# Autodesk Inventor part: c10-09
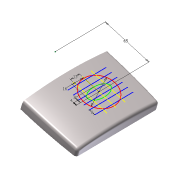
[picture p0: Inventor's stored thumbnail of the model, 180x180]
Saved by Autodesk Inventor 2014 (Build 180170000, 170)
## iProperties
Created: 2010-12
Part Number: c10-09
Material: Generic
Document SubType Name: Modeling
Designer: Thom Tremblay
Density: 1 g/cm^3
Appearance: Generic
Author: Thom Tremblay
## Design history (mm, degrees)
sketch "Sketch1"
  geometry: L1 (-60, -12)-(60, -12); L2 (60, -12)-(60, 12); L3 (60, 12)-(-60, 12); L4 (-60, 12)-(-60, -12); A1 r 350 centre (0, -332.819) between (60, 12) and (-60, 12); A2 r 350 centre (0, 332.819) between (-60, -12) and (60, -12); 3 further points
  constraints: 8 end point, 4 point on circle, 2 centre point, 2 midpoint, 2 parallel, 1 equal radius, 1 horizontal, 1 horizontal alignment, 1 perpendicular, 1 vertical alignment
  dimensions: "d0" = 120 distance of L3.end L2.end; "d1" = 24 distance of L2.end L1.end; "d2" = 350 radius of A1
workplane "Work Plane4"
sketch "Sketch5"
  geometry: L1 (-60, 12)-(-60, -12) reference; L2 (60, -12)-(60, 12) reference; L3 (-58, 10.314)-(-58, -10.314); L4 (58, -10.314)-(58, 10.314); A1 r 350 centre (0, 332.819) between (-60, -12) and (60, -12) reference; A2 r 350 centre (0, -332.819) between (60, 12) and (-60, 12) reference; A3 r 348 centre (0, 332.819) between (-58, -10.314) and (58, -10.314); A4 r 348 centre (0, -332.819) between (58, 10.314) and (-58, 10.314); 1 further point
  constraints: 4 end point, 4 point on circle, 2 centre point, 3 other
  dimensions: "d37" = 2 distance between parallel lines of L2 L4
sketch "Sketch6"
  geometry: L1 (-60, 0)-(60, 0); L2 (60, 0)-(58.843, 22.085); L3 (-60, 0)-(-58.779, 23.307); A1 r 691.758 centre (630.81, -36.204) between (-60, 0) and (-58, -100); A2 r 691.758 centre (-630.81, -36.204) between (58, -100) and (60, 0); 1 further point
  constraints: 6 end point, 4 point on circle, 2 centre point, 2 tangent, 1 horizontal
  dimensions: "d53" = 87 deg angle of L1 L3; "d54" = 87 deg angle of L1 L2 (= d53)
sketch "Sketch7"
  geometry: L1 (17.181, 0)-(12, 0) reference; L2 (15.181, -100)-(10.314, -100) reference; L3 (17.181, 0)-(16.768, 11.838); A1 r 911.322 centre (-893.585, -31.805) between (15.181, -100) and (17.181, 0); 1 further point
  constraints: 2 end point, 2 point on circle, 1 centre point, 1 tangent
  dimensions: "d56" = 88 deg angle of L1 L3
feature "LoftSrf2" sketch "Sketch5", "Sketch6", "Sketch7" dims "d57" = 0, "d58" = 90 deg, "d59" = 0, "d60" = 90 deg, "d61" = 0, "d62" = 90 deg, "d63" = 0, "d64" = 90 deg, "d65" = 0, "d66" = 90 deg
sketch "Sketch2"
  geometry: L1 (-75, -16)-(75, -16); L2 (-75, -60)-(75, -60); A1 r 183.781 centre (0, -183.781) between (75, -16) and (-75, -16); 2 further points
  constraints: 4 end point, 3 point on circle, 1 centre point, 1 coincident, 1 horizontal, 1 parallel
  dimensions: "d5" = 16 distance from line of point (0, 0) L1; "d7" = 60 distance from line of point (0, 0) L2; "d55" = 150 distance of L1.start L1.end
feature "RevolutionSrf1" sketch "Sketch2" dims angle "d8" = 40 deg
patch "Boundary Patch1" dims "d13" = 0, "d67" = 0, "d68" = 0, "d69" = 0, "d70" = 0
workplane "Work Plane1"
sketch "Sketch3"
  geometry: L1 (52, -85)-(52, -73); L2 (38, -73)-(38, -85); A1 r 7 centre (45, -73) between (52, -73) and (38, -73); A2 r 7 centre (45, -85) between (38, -85) and (52, -85); 1 further point
  constraints: 4 end point, 4 point on circle, 4 tangent, 2 centre point, 1 parallel, 1 vertical
  dimensions: "d15" = 12 distance of L1.start L1.end; "d16" = 7 radius of A1; "d50" = 45 horizontal distance of A1.centre point (0, 0); "d51" = 85 vertical distance of point (0, 0) A2.centre
extrude_surface "ExtrusionSrf2" sketch "Sketch3" dims "d19" = 14, "d20" = 5 deg
pattern_linear "Rectangular Pattern1" dims "d23" = 90
workplane "Work Plane2"
feature "Sculpt1"
sketch "Sketch4"
  geometry: L1 (-24.5, 6)-(24.5, 6); L2 (27.5, 3)-(27.5, -3); L3 (24.5, -6)-(-24.5, -6); L4 (-27.5, -3)-(-27.5, 3); A1 r 3 centre (-24.5, 3) between (-24.5, 6) and (-27.5, 3); A2 r 3 centre (24.5, 3) between (27.5, 3) and (24.5, 6); A3 r 3 centre (24.5, -3) between (24.5, -6) and (27.5, -3); A4 r 3 centre (-24.5, -3) between (-27.5, -3) and (-24.5, -6); 6 further points
  constraints: 8 end point, 8 point on circle, 8 tangent, 6 point on line, 4 centre point, 3 equal radius, 2 midpoint, 2 parallel, 1 horizontal, 1 horizontal alignment, 1 perpendicular, 1 vertical alignment
  dimensions: "d28" = 55 distance of point (27.5, -6) point (-27.5, -6); "d29" = 12 distance of point (27.5, 6) point (27.5, -6); "d30" = 3 radius of A1
extrude_surface "ExtrusionSrf6" sketch "Sketch4" dims "d31" = 14, "d32" = 45 deg
patch "Boundary Patch2" dims "d33" = 0, "d34" = 0
fillet "Fillet1" dims "d79" = 4, "d80" = 3, "d81" = 1
feature "Sculpt2"
node "Splitting Plane 1"
shell "Shell1" dims "d83" = 2
split "Split1"
  body "Solid1"
feature "Lip1" dims "d171" = 1, "d172" = 1, "d173" = 0, "d174" = 0, "d175" = 0, "d176" = 0
feature "Lip2" dims "d177" = 1, "d178" = 1, "d179" = 0, "d180" = 0, "d181" = 0, "d182" = 0.5
split "Split3"
  node "Back"
sketch "Sketch9"
  geometry: L1 (50.167, -73)-(50.167, -85) reference; L2 (39.833, -85)-(39.833, -73) reference; L3 (45, -73)-(45, -85); L4 (45, -85)-(39.833, -85); A1 r 5.167 centre (45, -73) between (50.167, -73) and (39.833, -73) reference; A2 r 5.167 centre (45, -85) between (39.833, -85) and (50.167, -85) reference; 5 further points
  constraints: 4 end point, 1 horizontal, 1 midpoint, 1 parallel, 1 perpendicular, 1 vertical, 3 other
  dimensions: "d86" = 90 distance of point (45, -79) point (-45, -79); "d89" = 40 distance of point (45, -79) point (45, -39)
  node "Projected Loop1"
feature "Boss1" dims "d92" = 0, "d93" = 0, "d94" = 7, "d95" = 2, "d96" = 0.5, "d97" = 6, "d98" = 1.25, "d99" = 3.5, "d100" = 2.5 deg, "d101" = 2.5 deg, "d102" = 2.5 deg, "d103" = 2.5 deg, "d104" = 90 deg, "d107" = 2, "d108" = 2, "d109" = 10, "d110" = 0, "d111" = 10 deg, "d112" = 2.5 deg, "d113" = 0, "d114" = 0, "d115" = 0, "d116" = 360 deg
feature "Boss2" dims "d117" = 3, "d118" = 0, "d119" = 6, "d120" = 3, "d121" = 9.5, "d122" = 2 deg, "d123" = 1 deg, "d126" = 2, "d127" = 2, "d128" = 10, "d129" = 0, "d130" = 10 deg, "d131" = 2.5 deg, "d132" = 0, "d133" = 0, "d134" = 0, "d135" = 360 deg
workplane "Work Plane6"
sketch "Sketch10"
  geometry: L1 (24, -85)-(-24, -85); L2 (-30, -79)-(-30, -51); L3 (-24, -45)-(24, -45); L4 (30, -51)-(30, -79); L5 (54.344, -100)-(-54.344, -100) reference; A1 r 6 centre (-24, -51) between (-24, -45) and (-30, -51); A2 r 6 centre (24, -51) between (30, -51) and (24, -45); A3 r 6 centre (24, -79) between (24, -85) and (30, -79); A4 r 6 centre (-24, -79) between (-30, -79) and (-24, -85); 5 further points
  constraints: 8 end point, 8 point on circle, 8 tangent, 6 point on line, 4 centre point, 3 equal radius, 2 parallel, 1 horizontal, 1 midpoint, 1 perpendicular, 1 vertical alignment
  dimensions: "d137" = 60 distance of point (-30, -45) point (30, -45); "d138" = 40 distance of point (-30, -85) point (-30, -45); "d139" = 15 distance between parallel lines of L5 L1; "d141" = 6 radius of A2
feature "Rest1" sketch "Sketch10" dims "d142" = 5, "d143" = 0, "d144" = 0, "d145" = 0, "d146" = 2 deg, "d147" = 2 deg, "d148" = 2
feature "Rule Fillet1" dims "d149" = 2, "d150" = 1
workplane "Work Plane7"
sketch "Sketch11" dims "d21" = 20, "d154" = 16, "d155" = 8, "d161" = 10, "d168" = 10
  geometry: L1 (-13, -39.858)-(-13, -90.142); L2 (-25.187, -85)-(29.449, -85); L3 (0, -39.858)-(0, -90.142); L4 (13, -39.858)-(13, -90.142); L5 (-25.187, -77)-(29.449, -77); L6 (-25.187, -69)-(29.449, -69); L7 (-25.187, -61)-(29.449, -61); L8 (-25.187, -53)-(29.449, -53); L9 (-25.187, -45)-(29.449, -45); C1 r 22.5 at (0, -65); 3 further points; 1 other entity
  constraints: 18 end point, 2 coincident, 2 vertical, 1 centre point, 1 horizontal, 1 midpoint, 1 perpendicular, 1 vertical alignment, 23 other
  dimensions: "d152" = 45 diameter of C1; "d153" = 65 distance of point (0, 0) C1.centre; "d158" = 13 distance of L1.start L3.start; "d165" = 8 distance of L2.start L5.start; "d170" = 4 distance from line of L7 point (0, -65)
body "Srf2"
body "Srf3"
body "Srf4"
body "Srf5"
body "Srf6"
body "Srf7"
body "Srf8"
body "Srf9"
body "Srf11"
feature "Stitch Surface1"
body "Srf12"
extrude_surface "ExtrusionSrf3"
extrude_surface "ExtrusionSrf4"
extrude_surface "ExtrusionSrf5"
node "Front"
node "Back - Top"
node "Back - Bottom"
other parameters: "d14" = -24, "d52" = -6
